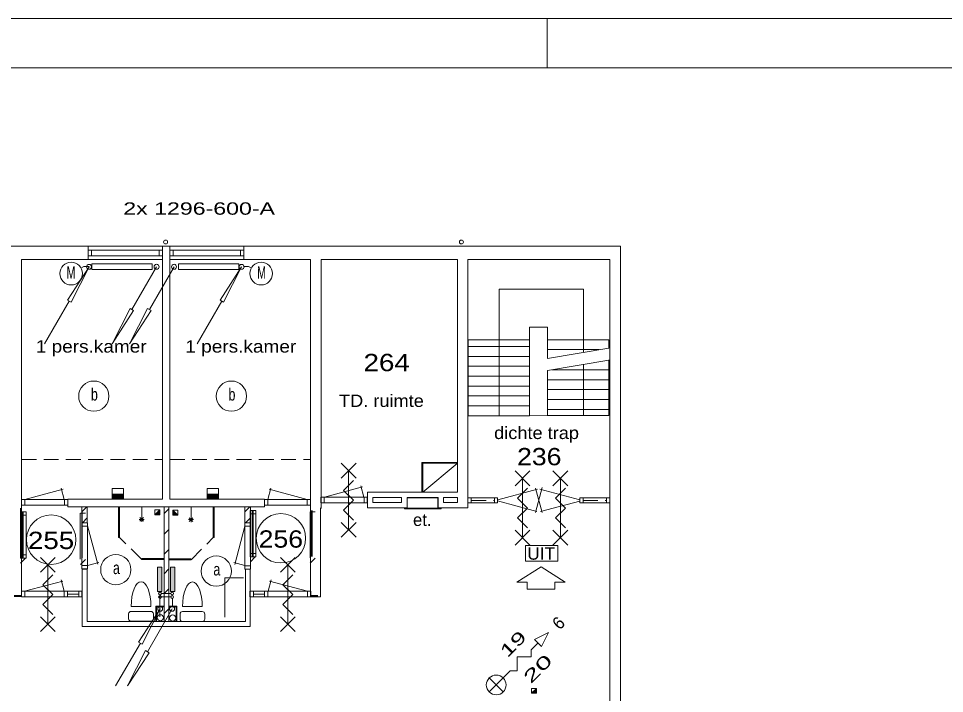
# Model space of a CAD drawing. Extents: x 295824 to 414724, y 24924 to 109024.
# Drawn here: x 320029 to 338765, y 95369 to 109024 of the extents above; entities that cross this region are included whole.
import ezdxf
from ezdxf.enums import TextEntityAlignment as Align

# ---------------------------------------------------------------- set-up
doc = ezdxf.new("R2010")
doc.units = 0
doc.header["$LTSCALE"] = 100
doc.linetypes.add('LONG_DASHED', pattern=[7.5, 6, -1.5])
doc.linetypes.add('MEDIUM_DASHED', pattern=[4.5, 3, -1.5])
for name, color, linetype, lineweight in [('1', 7, 'Continuous', 13), ('16', 7, 'Continuous', 13), ('61', 7, 'Continuous', 13)]:
    doc.layers.add(name, color=color, linetype=linetype, lineweight=lineweight)

msp = doc.modelspace()

# ---------------------------------------------------------------- hatches: boundary and pattern name
at = {"layer": '16'}
for points in [[(322152.7, 99315.2), (321921.2, 99315.2), (321921.2, 99401.7), (322152.7, 99401.7)], [(324077.6, 99315.2), (323846.1, 99315.2), (323846.1, 99401.7), (324077.6, 99401.7)], [(322843.9, 97923), (322929.4, 97923), (322929.4, 97430.8), (322843.9, 97430.8)], [(323103.1, 97923), (323188.5, 97923), (323188.5, 97430.8), (323103.1, 97430.8)]]:
    msp.add_hatch(color=256, dxfattribs=at).paths.add_polyline_path(points)
at = {"layer": '61'}
for points in [[(322789.5, 98985.1), (322889.5, 99085.1), (322889.5, 98985.1)], [(323251.9, 98979.7), (323151.9, 99079.7), (323151.9, 98979.7)], [(330408.1, 95372.4), (330508.1, 95472.4), (330508.1, 95372.4)]]:
    msp.add_hatch(color=256, dxfattribs=at).paths.add_polyline_path(points)

# ---------------------------------------------------------------- linework, layer by layer
at = {"layer": '1'}
msp.add_line((330723.6, 108023.8), (330723.6, 109023.8), dxfattribs=at)
for points in [[(414723.6, 109023.8), (304995.6, 109023.8), (295823.6, 109023.8)], [(304995.6, 25923.8), (413723.6, 25923.8), (413723.6, 108023.8), (304995.6, 108023.8)]]:
    msp.add_lwpolyline(points, dxfattribs=at)
at = {"layer": '16'}
for p, q in [((322822.5, 104000.9), (322322.5, 103134.9)), ((323175.9, 104000.9), (322675.9, 103134.9)), ((320555.8, 102441.9), (321055.8, 103307.9)), ((323642.5, 102441.9), (324142.5, 103307.9)), ((321921.2, 99401.7), (321921.2, 99515.6)), ((323846.1, 99401.7), (323846.1, 99515.6)), ((322891.2, 96917), (322891.2, 97356.6)), ((323111.5, 97392), (322919.8, 97392)), ((323137.1, 97080.9), (322637.1, 96214.9)), ((321994.5, 95522.9), (322494.5, 96388.9))]:
    msp.add_line(p, q, dxfattribs=at)
at = {"layer": '16', "linetype": 'LONG_DASHED'}
for p, q in [((322919.9, 97321.2), (323111.4, 97321.2)), ((323142.4, 97131.9), (323142.4, 97295.5))]:
    msp.add_line(p, q, dxfattribs=at)
at = {"layer": '16'}
for points in [[(321455.8, 104000.9), (321091.8, 103286.9), (321019.8, 103328.9)], [(321515.6, 103945.4), (322734.9, 103945.4), (322734.9, 104063.3), (321515.6, 104063.3)], [(323264.5, 103945.4), (324483.9, 103945.4), (324483.9, 104063.3), (323264.5, 104063.3)], [(324542.5, 104000.9), (324178.5, 103286.9), (324106.5, 103328.9)], [(321922.5, 102441.9), (322286.5, 103155.9), (322358.5, 103113.9)], [(322275.9, 102441.9), (322639.9, 103155.9), (322711.9, 103113.9)], [(322152.7, 99315.2), (321921.2, 99315.2), (321921.2, 99401.7), (322152.7, 99401.7)], [(324077.6, 99315.2), (323846.1, 99315.2), (323846.1, 99401.7), (324077.6, 99401.7)], [(322843.9, 97923), (322929.4, 97923), (322929.4, 97430.8), (322843.9, 97430.8)], [(323103.1, 97923), (323188.5, 97923), (323188.5, 97430.8), (323103.1, 97430.8)], [(322894.5, 97081.9), (322530.5, 96367.9), (322458.5, 96409.9)], [(322237.1, 95521.9), (322601.1, 96235.9), (322673.1, 96193.9)]]:
    msp.add_lwpolyline(points, close=True, dxfattribs=at)
for points in [[(321455.8, 104008.7), (321349.8, 104008.7), (321290.3, 103974.4)], [(324577.9, 104008.7), (324683.9, 104008.7), (324743.4, 103974.4)], [(322152.7, 99401.7), (322152.7, 99515.6), (321921.2, 99515.6)], [(324077.6, 99401.7), (324077.6, 99515.6), (323846.1, 99515.6)], [(324201.4, 96910.6), (324201.4, 97706.9), (324584, 97706.9)]]:
    msp.add_lwpolyline(points, dxfattribs=at)
for centre, radius in [((321094.7, 103863.4), 229.9), ((321455.8, 104000.6), 50), ((322822.5, 104001.3), 50), ((323175.9, 104001.3), 50), ((324542.5, 104000.6), 50), ((324939, 103863.4), 229.9), ((322892, 97389), 27.9), ((322892, 97321.2), 27.9), ((323139.4, 97392), 27.9), ((323139.4, 97321.2), 27.9), ((322894.5, 97081.6), 50), ((323137.1, 97081.2), 50)]:
    msp.add_circle(centre, radius, dxfattribs=at)
at = {"layer": '61'}
for p, q in [((321440.7, 104147.6), (321440.7, 104417.6)), ((322940.1, 104417.5), (322940.1, 99297.6)), ((323090.1, 104409.9), (323090.1, 99297.6)), ((324588.7, 104147.6), (324588.7, 104417.8)), ((332210.1, 104417.6), (332210.1, 87553.4)), ((321507.5, 104225.9), (321507.5, 104339.8)), ((322872.5, 104225.3), (322872.5, 104339.3)), ((323156, 104226.2), (323156, 104340.2)), ((324520.3, 104225.9), (324520.3, 104339.6)), ((320090.1, 104147.6), (322940.1, 104147.6)), ((320090.1, 97436.7), (320090.1, 104147.6)), ((325940.1, 104147.6), (323090.1, 104147.6)), ((325940.1, 97322.6), (325940.1, 104147.6)), ((330368.9, 102524.7), (330368.9, 102782.6)), ((330368.9, 102782.6), (330732.6, 102782.6)), ((330732.6, 102524.7), (330732.6, 102782.6)), ((331972.5, 102524.7), (330732.6, 102524.7)), ((331972.5, 102357.4), (331972.5, 102524.7)), ((329129, 102388.3), (330368.9, 102388.3)), ((330732.6, 102146.2), (331972.5, 102357.4)), ((331780.5, 102324.7), (330732.6, 102324.7)), ((329129, 102188.3), (330368.9, 102188.3)), ((330729.7, 101899.9), (331972.5, 102111.6)), ((329129, 101988.3), (330368.9, 101988.3)), ((331459.8, 102024.2), (331459.8, 100990.2)), ((329129, 101788.3), (330368.9, 101788.3)), ((331975.6, 101916.3), (330826.3, 101916.3)), ((329129, 101588.3), (330368.9, 101588.3)), ((331975.6, 101716.3), (330729.7, 101716.3)), ((329129, 101388.3), (330368.9, 101388.3)), ((331975.6, 101516.3), (330729.7, 101516.3)), ((329129, 101188.3), (330368.9, 101188.3)), ((331975.6, 101316.3), (330729.7, 101316.3)), ((329129, 100988.3), (330368.9, 100988.3)), ((331975.6, 101116.3), (330729.7, 101116.3)), ((326857.8, 100028.2), (326557.8, 99728.2)), ((326557.8, 100028.2), (326857.8, 99728.2)), ((326707.8, 98678.2), (326707.8, 99878.2)), ((328910.1, 100042.6), (328190.6, 100042.6)), ((328190.6, 100042.6), (328190.6, 99443.9)), ((328207.1, 99443.8), (328906.1, 100023.8)), ((330376.8, 99870.8), (330076.8, 99570.8)), ((330076.8, 99870.8), (330376.8, 99570.8)), ((331143.5, 99870.8), (330843.5, 99570.8)), ((330843.5, 99870.8), (331143.5, 99570.8)), ((330226.8, 98520.8), (330226.8, 99720.8)), ((330993.5, 98520.8), (330993.5, 99720.8)), ((320156.3, 99293.7), (320929, 99500.7)), ((320954.7, 99294.3), (320893.9, 99521.1)), ((325074.1, 99295.4), (325134.9, 99522.2)), ((325872.5, 99294.8), (325099.8, 99501.8)), ((326218.7, 99339.4), (326991.5, 99546.4)), ((327017.2, 99340), (326956.4, 99566.9)), ((329725.3, 99287.4), (330529.4, 99502.9)), ((330621.8, 99028), (330488.5, 99525.4)), ((330489.1, 99032.9), (330623.8, 99535.6)), ((330578.4, 99502.9), (331383.5, 99287.2)), ((326142.6, 99224.8), (326142.6, 99338.8)), ((326151.2, 99338.8), (327086.5, 99338.8)), ((326210.9, 99224.8), (326210.9, 99338.8)), ((327019.5, 99224.8), (327019.5, 99338.8)), ((327086.5, 99224.8), (327086.5, 99338.8)), ((328910.1, 99442.6), (327087.4, 99442.6)), ((327087.4, 99122.6), (327087.4, 99442.6)), ((327196.2, 99232.6), (327196.2, 99332.6)), ((327780.1, 99332.6), (327196.2, 99332.6)), ((327780.1, 99232.6), (327780.1, 99332.6)), ((327890.1, 99122.6), (327890.1, 99332.6)), ((328520.1, 99332.6), (327890.1, 99332.6)), ((327895, 99116.1), (327895, 99327.8)), ((327895, 99327.8), (328510.1, 99327.8)), ((328510.1, 99116.1), (328510.1, 99327.8)), ((328520.1, 99122.6), (328520.1, 99332.6)), ((328908.2, 99332.6), (328630.1, 99332.6)), ((328630.1, 99232.6), (328630.1, 99332.6)), ((328908.2, 99232.6), (328908.2, 99332.6)), ((329120.8, 99328.4), (329723.3, 99328.4)), ((329186.3, 99228.4), (329186.3, 99328.4)), ((329657.8, 99228.4), (329657.8, 99328.4)), ((329723.3, 99228.4), (329723.3, 99328.4)), ((331384.7, 99228.4), (331384.7, 99328.4)), ((331384.7, 99328.4), (331990.1, 99328.4)), ((331451.5, 99228.5), (331451.5, 99327.5)), ((331923.1, 99228.1), (331923.1, 99328.1)), ((320070.2, 98795.1), (320070.2, 99119.2)), ((320157.1, 99179), (320157.1, 99293)), ((320957.1, 99179), (320957.1, 99293)), ((321024.1, 99179), (321024.1, 99293)), ((321309.2, 99046.8), (321408.9, 99146.5)), ((321310.7, 98823), (321310.7, 99147)), ((321310.7, 99147), (321420.7, 99147)), ((321420.7, 98823), (321420.7, 99147)), ((322072, 99147.4), (322072, 98526.9)), ((322521.8, 98940.9), (322521.8, 99140.9)), ((322973.8, 99147.6), (322973.8, 96822.6)), ((323070.1, 99147.6), (323070.1, 96822.6)), ((323519.5, 98935.5), (323519.5, 99135.5)), ((323969.4, 99142), (323969.4, 98521.5)), ((324609.7, 98823), (324609.7, 99147)), ((324609.7, 99147), (324719.7, 99147)), ((324611.4, 99046.8), (324711.1, 99146.5)), ((324719.7, 98823), (324719.7, 99147)), ((325004.7, 99180.1), (325004.7, 99294.1)), ((325071.7, 99180.1), (325071.7, 99294.1)), ((325871.7, 99180.1), (325871.7, 99294.1)), ((326141.5, 97322.6), (326141.5, 99122.6)), ((327086.5, 99224.8), (326151.2, 99224.8)), ((327087.4, 99122.6), (327890.1, 99122.6)), ((327196.2, 99232.6), (327780.1, 99232.6)), ((327840.7, 99115.8), (328577.6, 99115.8)), ((327840.7, 99105.8), (327840.7, 99115.8)), ((328520.1, 99122.6), (329120.1, 99122.6)), ((328577.6, 99105.8), (328577.6, 99115.8)), ((328630.1, 99232.6), (328908.2, 99232.6)), ((329120.8, 99228.4), (329723.3, 99228.4)), ((329723.4, 99264.2), (330517.1, 99051.5)), ((330593.7, 99049.5), (331383.5, 99261.2)), ((331384.7, 99228.4), (331990.1, 99228.4)), ((331990.1, 99122.6), (331990.1, 94659.1)), ((320182.8, 98973.6), (320068.8, 98973.6)), ((320176.8, 99044.2), (320071.6, 99044.2)), ((320110.3, 98108.2), (320110.3, 99040.6)), ((320126.1, 98108.2), (320126.1, 99040.6)), ((320182.8, 98108.2), (320182.8, 99040.6)), ((321278.6, 98083), (321278.6, 99017)), ((321380.8, 99017.8), (321286.1, 99017.8)), ((321307.4, 98110.9), (321307.4, 99044.9)), ((321318.4, 98110.9), (321318.4, 99044.9)), ((322557.2, 98926.2), (322486.4, 98855.5)), ((322557.2, 98855.5), (322486.4, 98926.2)), ((322521.8, 98940.9), (322521.8, 98840.9)), ((322974.4, 99011.5), (323070.1, 99107.3)), ((323519.5, 98935.5), (323519.5, 98835.5)), ((324832.2, 99001.5), (324718.2, 99001.5)), ((324826.3, 99072.1), (324721, 99072.1)), ((324759.8, 98136.1), (324759.8, 99068.5)), ((324775.6, 98136.1), (324775.6, 99068.5)), ((324832.2, 98136.1), (324832.2, 99068.5)), ((325928, 98110.9), (325928, 99044.9)), ((326030.3, 99045.7), (325935.5, 99045.7)), ((325956.9, 98138.8), (325956.9, 99072.8)), ((325967.9, 98138.8), (325967.9, 99072.8)), ((327840.7, 99105.8), (328577.6, 99105.8)), ((321308.9, 98822.1), (321308.9, 97889.7)), ((321308.9, 98756.7), (321422.9, 98756.7)), ((321310.7, 98823), (321420.7, 98823)), ((321321.5, 98824.2), (321421.2, 98923.9)), ((321426.1, 98757.4), (321633.2, 97984.7)), ((322571.8, 98890.9), (322471.8, 98890.9)), ((323469.5, 98885.5), (323569.5, 98885.5)), ((323484.2, 98920.9), (323554.9, 98850.2)), ((323484.2, 98850.2), (323554.9, 98920.9)), ((324610.3, 98753.2), (324403.3, 97980.5)), ((324722.4, 98752.4), (324608.4, 98752.4)), ((324609, 98819.4), (324723, 98819.4)), ((324609.7, 98823), (324719.7, 98823)), ((324620, 98824.2), (324719.7, 98923.9)), ((324722.4, 98819.4), (324722.4, 97885.4)), ((326857.8, 98828.2), (326557.8, 98528.2)), ((326557.8, 98828.2), (326857.8, 98528.2)), ((322974.4, 98593.4), (323070.1, 98689.2)), ((330376.8, 98670.8), (330076.8, 98370.8)), ((330076.8, 98670.8), (330376.8, 98370.8)), ((331143.5, 98670.8), (330843.5, 98370.8)), ((330843.5, 98670.8), (331143.5, 98370.8)), ((322974.4, 98188.8), (323070.1, 98284.6)), ((324832.2, 98201.5), (324718.2, 98201.5)), ((320182.8, 98173.6), (320068.8, 98173.6)), ((320170.2, 98106.1), (320070.5, 98006.4)), ((320181, 98107.4), (320071, 98107.4)), ((320771, 98119.9), (320471, 97819.9)), ((320471, 98119.9), (320771, 97819.9)), ((321381, 98078.3), (321281.3, 97978.6)), ((321426.7, 97959), (321653.6, 98019.8)), ((322972, 98097.4), (322522.9, 98097.4)), ((322522.9, 98079.4), (322522.9, 98097.4)), ((322972.3, 98079.4), (322522.9, 98079.4)), ((323069, 98074), (323518.5, 98074)), ((323069.3, 98092), (323518.5, 98092)), ((323518.5, 98074), (323518.5, 98092)), ((324609.7, 97954.8), (324382.8, 98015.6)), ((324819.6, 98134), (324719.9, 98034.3)), ((324830.4, 98135.2), (324720.5, 98135.2)), ((325626.8, 98119.9), (325326.8, 97819.9)), ((325326.8, 98119.9), (325626.8, 97819.9)), ((326030.4, 98106.1), (325930.7, 98006.4)), ((320621, 96769.9), (320621, 97969.9)), ((321308.9, 97956.7), (321422.9, 97956.7)), ((321314.9, 97886.1), (321314.9, 97320.2)), ((321314.9, 97886.1), (321420.1, 97886.1)), ((322974.4, 97792.8), (323070.1, 97888.6)), ((324722.4, 97952.4), (324608.4, 97952.4)), ((324620.1, 97884.6), (324620.1, 96822.6)), ((324620.1, 97884.6), (324714.9, 97884.6)), ((324714.9, 97884.6), (324714.9, 97422.6)), ((325476.8, 96769.9), (325476.8, 97969.9)), ((320152.9, 97437.3), (320925.7, 97644.4)), ((320951.3, 97437.9), (320890.6, 97664.8)), ((325078.7, 97437.9), (325139.4, 97664.8)), ((325877.1, 97437.3), (325104.3, 97644.4)), ((320153.7, 97322.7), (320153.7, 97436.7)), ((320953.7, 97322.7), (320953.7, 97436.7)), ((321020.7, 97322.7), (321020.7, 97436.7)), ((321246.7, 97322.7), (321246.7, 97436.7)), ((322974.4, 97389.4), (323070.1, 97485.2)), ((324783.3, 97322.7), (324783.3, 97436.7)), ((325009.3, 97322.7), (325009.3, 97436.7)), ((325076.3, 97322.7), (325076.3, 97436.7)), ((325876.3, 97322.7), (325876.3, 97436.7)), ((319943.6, 97348.9), (320084.8, 97348.9)), ((319943.6, 97333.9), (320084.8, 97333.9)), ((321246.7, 97376.8), (321020.7, 97376.8)), ((324783.3, 97376.8), (325009.3, 97376.8)), ((325931.5, 97322.6), (326141.5, 97322.6)), ((325942.4, 97348.9), (326083.6, 97348.9)), ((325942.4, 97333.9), (326083.6, 97333.9)), ((322707.5, 97130.5), (322307.5, 97130.5)), ((322820, 97123.1), (322970, 97123.1)), ((322820, 96823.1), (322820, 97123.1)), ((322974.4, 96988.5), (323070.1, 97084.3)), ((323070.1, 97122.6), (323220.1, 97122.6)), ((323220.1, 97122.6), (323220.1, 96822.6)), ((323746.9, 97125.6), (323346.9, 97125.6)), ((320771, 96919.9), (320471, 96619.9)), ((320471, 96919.9), (320771, 96619.9)), ((322257.5, 96880.5), (322257.5, 96980.5)), ((322307.5, 97030.5), (322707.5, 97030.5)), ((322757.5, 96980.5), (322757.5, 96880.5)), ((323296.9, 96875.6), (323296.9, 96975.6)), ((323346.9, 97025.6), (323746.9, 97025.6)), ((323796.9, 96975.6), (323796.9, 96875.6)), ((325626.8, 96919.9), (325326.8, 96619.9)), ((325326.8, 96919.9), (325626.8, 96619.9)), ((322707.5, 96830.5), (322307.5, 96830.5)), ((323746.9, 96825.6), (323346.9, 96825.6)), ((329835.6, 95401.3), (329552.8, 95684.1))]:
    msp.add_line(p, q, dxfattribs=at)
at = {"layer": '61', "linetype": 'MEDIUM_DASHED'}
for p, q in [((320089.5, 100101), (322938.6, 100101)), ((323091.9, 100101), (325938.9, 100101)), ((329188.3, 99274.8), (329658.2, 99274.8)), ((331450.5, 99272.3), (331922.9, 99272.3)), ((322520.8, 98079.8), (322073.9, 98526.7)), ((323520.5, 98074.4), (323967.4, 98521.3))]:
    msp.add_line(p, q, dxfattribs=at)
at = {"layer": '61'}
for points in [[(301796.6, 92184.5), (301820.1, 104417.6), (332210.1, 104417.6)], [(326150.1, 99110.7), (326150.1, 104147.6), (328910.1, 104147.6), (328910.1, 99442.6)], [(329120.1, 99122.6), (329120.1, 104147.6), (331990.1, 104147.6), (331990.1, 99120.9)], [(329757.2, 100988.3), (329757.2, 103549), (331460, 103549), (331460, 102270.1)], [(331972.5, 102524.7), (330732.6, 102524.7), (330732.6, 102146.2)], [(330729.7, 100990.2), (331975.6, 100990.2), (331975.6, 102116.3)], [(330729.7, 101899.9), (330729.7, 100990.2), (330368.9, 100988.3)], [(328910.1, 100027.6), (328207.4, 100027.6), (328207.4, 99442.6)], [(326807.8, 98878.2), (326607.8, 99078.2), (326807.8, 99278.2), (326607.8, 99478.2), (326807.8, 99678.2)], [(330326.8, 98720.8), (330126.8, 98920.8), (330326.8, 99120.8), (330126.8, 99320.8), (330326.8, 99520.8)], [(331093.5, 98720.8), (330893.5, 98920.8), (331093.5, 99120.8), (330893.5, 99320.8), (331093.5, 99520.8)], [(320090.1, 99179), (320090.1, 99293), (321024.1, 99293)], [(321024.1, 99179), (320090.1, 99179), (320090.1, 99293)], [(322939.9, 99297.6), (321024.9, 99297.6), (321024.9, 99147.6), (325004.2, 99147.6)], [(322054, 99147.4), (322054, 98526.9), (322072, 98526.9)], [(323089.9, 99297.6), (325004.2, 99297.6), (325004.2, 99147.6)], [(323987.4, 99142), (323987.4, 98521.5), (323969.4, 98521.5)], [(325938.7, 99180.1), (325938.7, 99294.1), (325004.7, 99294.1)], [(325004.7, 99180.1), (325938.7, 99180.1), (325938.7, 99294.1)], [(322889.5, 99085.1), (322889.5, 98985.1), (322789.5, 98985.1)], [(323151.9, 99079.7), (323151.9, 98979.7), (323251.9, 98979.7)], [(321420.1, 97886.1), (321420.1, 96822.6), (324620.1, 96822.6)], [(320721, 96969.9), (320521, 97169.9), (320721, 97369.9), (320521, 97569.9), (320721, 97769.9)], [(325576.8, 96969.9), (325376.8, 97169.9), (325576.8, 97369.9), (325376.8, 97569.9), (325576.8, 97769.9)], [(321314.9, 97322.6), (321314.9, 96722.6), (324714.9, 96722.6), (324714.9, 97322.6)], [(322805, 96823.1), (322805, 97138.1), (322970, 97138.1)], [(323070.1, 97137.6), (323235.1, 97137.6), (323235.1, 96822.6)], [(329552.8, 95401.3), (329977, 95825.6), (330118.4, 95825.5), (330118.4, 96108.4), (330401.3, 96108.4), (330401.3, 96249.8), (330542.7, 96391.2)], [(330508.1, 95472.4), (330508.1, 95372.4), (330408.1, 95372.4)]]:
    msp.add_lwpolyline(points, dxfattribs=at)
for points in [[(321440.6, 104225.8), (321440.6, 104339.8), (322939.3, 104339.8), (322939.3, 104225.8)], [(323089.6, 104225.9), (323089.6, 104339.9), (324589, 104339.9), (324589, 104225.9)], [(330368.9, 102524.7), (329129, 102524.7), (329129, 100988.3), (330368.9, 100988.3)], [(320182.8, 99041.6), (320068.8, 99041.6), (320068.8, 98107.6), (320182.8, 98107.6)], [(322889.5, 99085.1), (322789.5, 99085.1), (322789.5, 98985.1)], [(322789.5, 98985.1), (322889.5, 99085.1), (322889.5, 98985.1)], [(323151.9, 99079.7), (323251.9, 99079.7), (323251.9, 98979.7)], [(323251.9, 98979.7), (323151.9, 99079.7), (323151.9, 98979.7)], [(324832.2, 99069.4), (324718.2, 99069.4), (324718.2, 98135.4), (324832.2, 98135.4)], [(321308.9, 97888.7), (321422.9, 97888.7), (321422.9, 98822.7), (321308.9, 98822.7)], [(324722.4, 98819.4), (324722.4, 97885.4), (324608.4, 97885.4), (324608.4, 98819.4)], [(330284.1, 98044.6), (330940.7, 98044.6), (330940.7, 98365.6), (330284.1, 98365.6)], [(330881, 97479.4), (330321, 97479.4), (330321, 97619.4), (330111, 97619.4), (330601, 97934.4), (331091, 97619.4), (330881, 97619.4)], [(320086.7, 97322.7), (320086.7, 97436.7), (321313.1, 97436.7), (321313.1, 97322.7)], [(320086.7, 97322.7), (320086.7, 97436.7), (321313.1, 97436.7), (321313.1, 97322.7)], [(324708, 97322.7), (324708, 97436.7), (325935, 97436.7), (325935, 97322.7)], [(324716.3, 97322.7), (324716.3, 97436.7), (325943.3, 97436.7), (325943.3, 97322.7)], [(330472, 96461.9), (330613.4, 96320.5), (330754.8, 96603.4)], [(330508.1, 95472.4), (330408.1, 95472.4), (330408.1, 95372.4)], [(330408.1, 95372.4), (330508.1, 95472.4), (330508.1, 95372.4)]]:
    msp.add_lwpolyline(points, close=True, dxfattribs=at)
for centre, radius in [((323005.3, 104502.7), 40), ((328990.8, 104502.7), 40), ((321552.2, 101384.2), 306.3), ((324336.3, 101384.2), 306.3), ((320688.9, 98481.1), 500), ((325338.3, 98509), 500), ((321997.6, 97873.7), 306.3), ((324030, 97845.8), 306.3), ((322897.6, 96900.6), 62.5), ((323147.6, 96895), 62.5), ((329694.2, 95542.7), 200)]:
    msp.add_circle(centre, radius, dxfattribs=at)
for centre, start, end in [((322307.5, 96980.5), 90, 180), ((322307.5, 96880.5), 180, 270), ((322707.5, 96980.5), 0, 90), ((322707.5, 96880.5), 270, 0), ((323346.9, 96975.6), 90, 180), ((323346.9, 96875.6), 180, 270), ((323746.9, 96975.6), 0, 90), ((323746.9, 96875.6), 270, 0)]:
    msp.add_arc(centre, 50, start, end, dxfattribs=at)
for centre in [(322507.5, 97130.5), (323546.9, 97125.6)]:
    msp.add_ellipse(centre, major_axis=(0, 500), ratio=0.4, start_param=4.712389, end_param=7.8539816, dxfattribs=at)

# ---------------------------------------------------------------- texts
at = {"layer": '16'}
for s, width, p in [('2x 1296-600-A', 1.4, (322148, 105054.9)), ('M', 0.65, (321000.7, 103760.3)), ('M', 0.65, (324855.9, 103760.3))]:
    msp.add_text(s, height=250, dxfattribs=dict(at, width=width)).set_placement(p)
at = {"layer": '61'}
for s, height, width, p in [('1 pers.kamer', 250, 1.15, (320377.7, 102265.6)), ('1 pers.kamer', 250, 1.15, (323404.8, 102265.6)), ('264', 350, 1.2, (327010, 101889.5)), ('b', 250, 0.75, (321494.2, 101295)), ('b', 250, 0.75, (324278.3, 101295)), ('TD. ruimte', 250, 1.1, (326513.7, 101166)), ('dichte trap', 250, 1.1, (329652.6, 100516.4)), ('236', 350, 1.15, (330116.5, 99985.9)), ('UIT', 250, 1.05, (330322.3, 98075.2)), ('a', 250, 0.75, (321939.6, 97784.5)), ('a', 250, 0.75, (323972, 97756.6))]:
    msp.add_text(s, height=height, dxfattribs=dict(at, width=width)).set_placement(p)
msp.add_text('et.', height=250, dxfattribs=at).set_placement((328012, 98758))
for s, width, p in [('255', 1.2, (320687.3, 98291.2)), ('256', 1.15, (325336.8, 98319.1))]:
    msp.add_text(s, height=350, dxfattribs=dict(at, width=width)).set_placement(p, align=Align.CENTER)
msp.add_text('6', height=250, rotation=45, dxfattribs=at).set_placement((330977.5, 96641.1))
for s, width, p in [('19', 1.55, (329921.2, 96079.6)), ('20', 1.75, (330393.5, 95551.1))]:
    msp.add_text(s, height=250, rotation=45, dxfattribs=dict(at, width=width)).set_placement(p)

doc.saveas('drawing.dxf')
